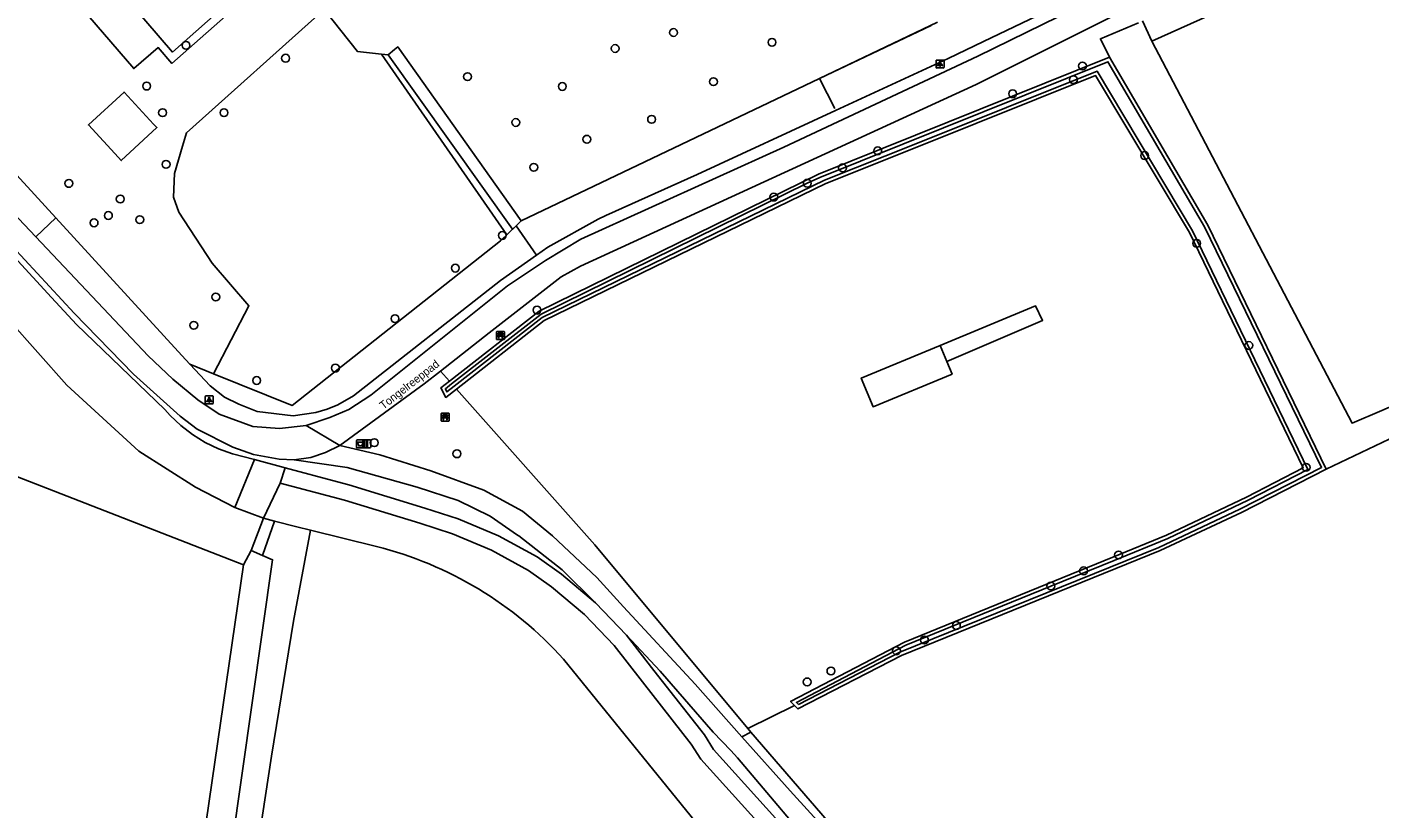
# Model space of a CAD drawing. Extents: x 160203 to 161526, y 379529 to 381797.
# Drawn here: x 161056.6 to 161225.7, y 381138.1 to 381235.8 of the extents above; entities that cross this region are included whole.
import ezdxf

# ---------------------------------------------------------------- set-up
doc = ezdxf.new("R2010")
doc.units = 0
for name, color, linetype in [('IMGEO_Afvalbak', 7, 'Continuous'), ('IMGEO_Bank', 7, 'Continuous'), ('IMGEO_Boom', 7, 'Continuous'), ('IMGEO_Bouwland', 7, 'Continuous'), ('IMGEO_Grasland_agrarisch', 7, 'Continuous'), ('IMGEO_Grasland_overig', 7, 'Continuous'), ('IMGEO_Groenvoorziening', 7, 'Continuous'), ('IMGEO_Haag', 7, 'Continuous'), ('IMGEO_Hek', 7, 'Continuous'), ('IMGEO_Lichtpunt', 7, 'Continuous'), ('IMGEO_Loofbos', 7, 'Continuous'), ('IMGEO_Openbare_ruimte_label', 7, 'Continuous'), ('IMGEO_Overkapping', 7, 'Continuous'), ('IMGEO_Pand', 7, 'Continuous'), ('IMGEO_Rijbaan_lokaal_gesloten', 7, 'Continuous'), ('IMGEO_Verkeersbordpaal', 7, 'Continuous'), ('IMGEO_Voetpad_halfverhard', 7, 'Continuous'), ('IMGEO_Waterloop', 7, 'Continuous')]:
    doc.layers.add(name, color=color, linetype=linetype)

msp = doc.modelspace()

# ---------------------------------------------------------------- linework, layer by layer
at = {"layer": 'IMGEO_Afvalbak'}
for p, q in [((161097.79, 381183.3), (161097.79, 381184.1)), ((161097.79, 381184.1), (161097.79, 381183.3)), ((161097.89, 381184.2), (161098.67, 381184.2)), ((161098.67, 381184.2), (161097.89, 381184.2)), ((161098.67, 381183.2), (161097.89, 381183.2)), ((161097.89, 381183.2), (161098.67, 381183.2)), ((161098.77, 381184.1), (161098.77, 381183.3)), ((161098.77, 381183.3), (161098.77, 381184.1))]:
    msp.add_line(p, q, dxfattribs=at)
msp.add_lwpolyline([(161097.93, 381183.91), (161098.63, 381183.91), (161098.48, 381183.44), (161098.08, 381183.44), (161097.93, 381183.91)], dxfattribs=at)
for centre, start, end in [((161097.89, 381184.1), 90, 180), ((161097.89, 381184.1), 90, 180), ((161097.89, 381183.3), 180, 270), ((161097.89, 381183.3), 180, 270), ((161098.67, 381184.1), 0, 90), ((161098.67, 381184.1), 360, 90), ((161098.67, 381183.3), 270, 0), ((161098.67, 381183.3), 270, 0)]:
    msp.add_arc(centre, 0.1, start, end, dxfattribs=at)
at = {"layer": 'IMGEO_Bank'}
for p, q in [((161115.28, 381196.83), (161115.28, 381197.67)), ((161115.28, 381197.67), (161115.28, 381196.83)), ((161115.36, 381197.75), (161116.2, 381197.75)), ((161116.2, 381197.75), (161115.36, 381197.75)), ((161116.21, 381196.76), (161115.37, 381196.76)), ((161115.37, 381196.76), (161116.21, 381196.76)), ((161115.59, 381197.26), (161115.59, 381197.37)), ((161115.98, 381197.15), (161115.59, 381197.15)), ((161115.92, 381197.37), (161115.64, 381197.37)), ((161115.64, 381197.37), (161115.64, 381197.26)), ((161115.64, 381197.26), (161115.92, 381197.26)), ((161115.93, 381197.26), (161115.93, 381197.37)), ((161115.97, 381197.37), (161115.97, 381197.26)), ((161116.28, 381197.68), (161116.28, 381196.84)), ((161116.28, 381196.84), (161116.28, 381197.68)), ((161108.37, 381186.62), (161108.37, 381187.46)), ((161108.37, 381187.46), (161108.37, 381186.62)), ((161108.44, 381187.55), (161109.29, 381187.55)), ((161109.29, 381187.55), (161108.44, 381187.55)), ((161109.3, 381186.55), (161108.45, 381186.55)), ((161108.45, 381186.55), (161109.3, 381186.55)), ((161109.07, 381186.94), (161108.67, 381186.94)), ((161108.68, 381187.05), (161108.68, 381187.16)), ((161108.72, 381187.16), (161108.72, 381187.05)), ((161109.01, 381187.16), (161108.73, 381187.16)), ((161108.73, 381187.05), (161109.01, 381187.05)), ((161109.02, 381187.05), (161109.02, 381187.16)), ((161109.06, 381187.16), (161109.06, 381187.05)), ((161109.37, 381187.47), (161109.37, 381186.63)), ((161109.37, 381186.63), (161109.37, 381187.47))]:
    msp.add_line(p, q, dxfattribs=at)
for points in [[(161115.53, 381197.15), (161115.39, 381197.15), (161115.5, 381197.26), (161115.59, 381197.26)], [(161115.59, 381197.37), (161115.5, 381197.37), (161115.5, 381197.53), (161116.06, 381197.53), (161116.06, 381197.37), (161115.98, 381197.37)], [(161115.58, 381197.15), (161115.58, 381196.94), (161115.54, 381196.94), (161115.54, 381197.15)], [(161115.98, 381197.26), (161116.06, 381197.26), (161116.18, 381197.15), (161116.04, 381197.15)], [(161116.03, 381197.15), (161116.03, 381196.94), (161115.99, 381196.94), (161115.99, 381197.15)], [(161108.62, 381186.94), (161108.47, 381186.94), (161108.59, 381187.05), (161108.67, 381187.05)], [(161108.67, 381187.16), (161108.59, 381187.16), (161108.59, 381187.33), (161109.15, 381187.33), (161109.15, 381187.16), (161109.07, 381187.16)], [(161108.67, 381186.94), (161108.67, 381186.73), (161108.62, 381186.73), (161108.62, 381186.94)], [(161109.07, 381187.05), (161109.15, 381187.05), (161109.26, 381186.94), (161109.12, 381186.94)], [(161109.12, 381186.94), (161109.12, 381186.73), (161109.07, 381186.73), (161109.07, 381186.94)]]:
    msp.add_lwpolyline(points, dxfattribs=at)
for centre, radius, start, end in [((161115.36, 381197.68), 0.0779, 92.4484, 184.2845), ((161115.36, 381197.68), 0.0779, 92.4484, 184.2845), ((161115.36, 381196.83), 0.0779, 182.4484, 274.2845), ((161115.36, 381196.83), 0.0779, 182.4484, 274.2845), ((161115.53, 381197.15), 0.00671, 2.8957, 87.1043), ((161115.59, 381197.15), 0.00671, 92.8957, 177.1043), ((161115.59, 381197.37), 0.00671, 2.8957, 87.1043), ((161115.59, 381197.26), 0.00671, 272.8957, 357.1043), ((161115.64, 381197.37), 0.00671, 92.8957, 177.1043), ((161115.64, 381197.26), 0.00671, 182.8957, 267.1043), ((161115.92, 381197.37), 0.00671, 2.8957, 87.1043), ((161115.92, 381197.26), 0.00671, 272.8957, 357.1043), ((161115.98, 381197.37), 0.00671, 92.8957, 177.1043), ((161115.98, 381197.26), 0.00671, 182.8957, 267.1043), ((161115.98, 381197.15), 0.00671, 2.8957, 87.1043), ((161116.04, 381197.15), 0.00671, 92.8957, 177.1043), ((161116.21, 381197.68), 0.0779, 2.4484, 94.2845), ((161116.21, 381197.68), 0.0779, 2.4484, 94.2845), ((161116.21, 381196.83), 0.0779, 272.4484, 4.2845), ((161116.21, 381196.83), 0.0779, 272.4484, 4.2845), ((161108.45, 381187.47), 0.0779, 92.4484, 184.2845), ((161108.45, 381187.47), 0.0779, 92.4484, 184.2845), ((161108.45, 381186.63), 0.0779, 182.4484, 274.2845), ((161108.45, 381186.63), 0.0779, 182.4484, 274.2845), ((161108.62, 381186.94), 0.00671, 2.8957, 87.1043), ((161108.67, 381187.16), 0.00671, 2.8957, 87.1043), ((161108.67, 381187.05), 0.00671, 272.8957, 357.1043), ((161108.67, 381186.94), 0.00671, 92.8957, 177.1043), ((161108.73, 381187.16), 0.00671, 92.8957, 177.1043), ((161108.73, 381187.05), 0.00671, 182.8957, 267.1043), ((161109.01, 381187.16), 0.00671, 2.8957, 87.1043), ((161109.01, 381187.05), 0.00671, 272.8957, 357.1043), ((161109.07, 381187.16), 0.00671, 92.8957, 177.1043), ((161109.07, 381187.05), 0.00671, 182.8957, 267.1043), ((161109.07, 381186.94), 0.00671, 2.8957, 87.1043), ((161109.12, 381186.94), 0.00671, 92.8957, 177.1043), ((161109.29, 381187.47), 0.0779, 2.4484, 94.2845), ((161109.29, 381187.47), 0.0779, 2.4484, 94.2845), ((161109.29, 381186.63), 0.0779, 272.4484, 4.2845), ((161109.29, 381186.63), 0.0779, 272.4484, 4.2845)]:
    msp.add_arc(centre, radius, start, end, dxfattribs=at)
at = {"layer": 'IMGEO_Boom'}
for centre in [(161137.41, 381235.13), (161076.48, 381233.53), (161149.72, 381233.91), (161088.93, 381231.92), (161130.11, 381233.14), (161188.51, 381230.95), (161071.57, 381228.44), (161111.67, 381229.62), (161123.52, 381228.39), (161142.4, 381228.99), (161187.38, 381229.24), (161179.79, 381227.48), (161073.56, 381225.11), (161081.23, 381225.11), (161117.7, 381223.89), (161134.67, 381224.28), (161126.58, 381221.79), (161162.93, 381220.34), (161196.28, 381219.75), (161074, 381218.65), (161119.95, 381218.28), (161158.53, 381218.21), (161154.12, 381216.29), (161061.85, 381216.27), (161068.27, 381214.32), (161149.94, 381214.56), (161065, 381211.34), (161066.79, 381212.25), (161070.71, 381211.74), (161116.02, 381209.76), (161202.78, 381208.77), (161110.15, 381205.68), (161080.21, 381202.07), (161120.35, 381200.43), (161077.46, 381198.53), (161102.61, 381199.36), (161209.31, 381196.01), (161095.16, 381193.18), (161085.32, 381191.63), (161100.01, 381183.85), (161110.34, 381182.47), (161216.46, 381180.77), (161193.02, 381169.81), (161188.65, 381167.83), (161184.56, 381165.93), (161172.76, 381160.99), (161168.76, 381159.18), (161165.27, 381157.83), (161154.11, 381153.94), (161157.08, 381155.31)]:
    msp.add_circle(centre, 0.489, dxfattribs=at)
at = {"layer": 'IMGEO_Bouwland'}
msp.add_lwpolyline([(161013.52, 381196.31), (161034.78, 381187.91), (161053.72, 381180.26), (161083.68, 381168.57)], dxfattribs=at)
at = {"layer": 'IMGEO_Grasland_agrarisch'}
for points in [[(161079.94, 381192.47), (161084.34, 381200.96), (161079.74, 381206.3), (161075.58, 381212.66), (161074.91, 381214.56), (161075.03, 381217.51), (161076.07, 381220.93), (161076.55, 381222.59), (161093.77, 381238.02)], [(161100.9, 381232.41), (161097.9, 381232.77), (161093.77, 381238.02)], [(161110.28, 381190.56), (161121.23, 381199.12), (161156.45, 381216.26), (161167.83, 381220.82), (161190.15, 381229.76), (161201.89, 381210.15), (161216.08, 381180.71), (161209.03, 381177.05), (161199.02, 381172.29), (161192.29, 381169.54), (161166.26, 381158.93), (161152.04, 381151.5), (161152.51, 381151.01)], [(161116.57, 381209.85), (161115.79, 381209.1), (161089.76, 381188.52), (161079.94, 381192.47)], [(161146.68, 381148.12), (161127.59, 381171.07), (161110.28, 381190.56)], [(161152.51, 381151.01), (161152.96, 381150.56), (161165.88, 381157.25), (161198.24, 381170.36), (161208.37, 381175.12), (161218.98, 381180.56)], [(161092.05, 381172.91), (161089.92, 381161.52), (161087.18, 381144.65), (161081.65, 381108.3), (161075.65, 381065.23), (161074.96, 381058.01)], [(161146.68, 381148.12), (161152.51, 381151.01)], [(161147.07, 381147.65), (161146.68, 381148.12)]]:
    msp.add_lwpolyline(points, dxfattribs=at)
at = {"layer": 'IMGEO_Grasland_overig'}
for points in [[(161367.83, 381310.71), (161294.02, 381278.51), (161294.05, 381277.58), (161293.85, 381277.49), (161232.69, 381250), (161197.17, 381234.04)], [(161120.28, 381207.29), (161121.7, 381208.28), (161128, 381211.79), (161128.95, 381212.25), (161140.38, 381217.39), (161157.67, 381225.4), (161171.71, 381231.9), (161176.13, 381234.01), (161209.5, 381250), (161221.3, 381255.61), (161240.99, 381264.56), (161246.29, 381266.89)], [(161036.74, 381238.05), (161041.49, 381232.45), (161060.22, 381211.97)], [(161118.36, 381211.58), (161155.67, 381229.38), (161169.59, 381236.02)], [(161195.51, 381236.36), (161190.76, 381234.35), (161191.89, 381232.05)], [(161197.17, 381234.04), (161196.03, 381236.58)], [(161263.14, 381204.2), (161225.91, 381187.89), (161222.21, 381186.3), (161197.17, 381234.04)], [(161101.77, 381232.33), (161100.9, 381232.41)], [(161100.9, 381232.41), (161116.57, 381209.85)], [(161191.89, 381232.05), (161155.51, 381217.41), (161120.61, 381200.3), (161109.4, 381191.55)], [(161191.89, 381232.05), (161204.16, 381211.06), (161218.98, 381180.56)], [(161060.22, 381211.97), (161057.71, 381209.57)], [(161060.22, 381211.97), (161075.97, 381194.74), (161076.98, 381193.66)], [(161116.57, 381209.85), (161117.29, 381210.54)], [(161120.28, 381207.29), (161117.74, 381210.98)], [(161076.98, 381193.66), (161079.5, 381190.95), (161081.3, 381189.56), (161083.08, 381188.65), (161085.4, 381187.75), (161089.86, 381187.22), (161092.71, 381187.64), (161094.12, 381188.05), (161095.48, 381188.6), (161097.43, 381189.73), (161115.8, 381204.13), (161120.28, 381207.29)], [(161170.74, 381195.99), (161182.64, 381200.98), (161183.52, 381199.13), (161171.56, 381194.01)], [(161109.4, 381191.55), (161108.29, 381192.8)], [(161218.98, 381180.56), (161227.72, 381184.71)], [(161085.05, 381181.74), (161088.87, 381180.71)], [(161086.17, 381174.41), (161082.58, 381175.75)], [(161145.96, 381147.09), (161147.07, 381147.65)], [(161175.22, 381116.21), (161164.8, 381127.1), (161147.07, 381147.65)]]:
    msp.add_lwpolyline(points, dxfattribs=at)
at = {"layer": 'IMGEO_Groenvoorziening'}
for points in [[(161081.37, 381241.6), (161083.54, 381239.04), (161074.73, 381231.27), (161073.02, 381233.25), (161069.95, 381230.62), (161054, 381249.19)], [(161076.98, 381193.66), (161079.94, 381192.47)], [(161109.4, 381191.55), (161108.33, 381190.71), (161108.95, 381189.52), (161110.28, 381190.56)], [(161086.05, 381169.75), (161087.55, 381174.03)]]:
    msp.add_lwpolyline(points, dxfattribs=at)
at = {"layer": 'IMGEO_Haag'}
for points in [[(161101.77, 381232.33), (161102.55, 381233), (161102.95, 381233.34), (161118.36, 381211.58)], [(161117.29, 381210.54), (161101.77, 381232.33)], [(161117.74, 381210.98), (161117.29, 381210.54)], [(161117.74, 381210.98), (161118.36, 381211.58)]]:
    msp.add_lwpolyline(points, dxfattribs=at)
at = {"layer": 'IMGEO_Hek'}
for points in [[(161170.4, 381236.41), (161155.67, 381229.38)], [(161155.67, 381229.38), (161118.36, 381211.58), (161117.74, 381210.98)], [(161155.67, 381229.38), (161157.55, 381225.64)], [(161036.27, 381227.49), (161059.7, 381201.99), (161062.8, 381198.62), (161073.83, 381188.01), (161074.49, 381187.27), (161075.83, 381185.99), (161077.3, 381184.86), (161078.89, 381183.89), (161080.56, 381183.09), (161082.31, 381182.47), (161085.05, 381181.74)], [(161117.74, 381210.98), (161115.79, 381209.1), (161089.76, 381188.52), (161079.94, 381192.47), (161076.98, 381193.66)], [(161227.72, 381184.71), (161218.98, 381180.56)], [(161141.26, 381147.32), (161134.95, 381155.38), (161131.53, 381159.79), (161127.66, 381163.81), (161123.39, 381167.41), (161120.35, 381169.56), (161115.55, 381172.21), (161110.5, 381174.35), (161106.32, 381175.67), (161096.85, 381178.57), (161095.42, 381178.96), (161088.87, 381180.71)], [(161088.27, 381178.8), (161086.17, 381174.41)], [(161086.17, 381174.41), (161084.61, 381170.36)], [(161142.41, 381145.5), (161155.58, 381130.91), (161167.52, 381117.41), (161170.51, 381113.56), (161172.88, 381109.71)]]:
    msp.add_lwpolyline(points, dxfattribs=at)
at = {"layer": 'IMGEO_Lichtpunt'}
for p, q in [((161170.21, 381231.6), (161170.21, 381230.79)), ((161170.21, 381231.6), (161170.21, 381230.79)), ((161171.11, 381231.69), (161170.31, 381231.69)), ((161171.11, 381231.69), (161170.31, 381231.69)), ((161170.31, 381230.7), (161171.11, 381230.7)), ((161170.31, 381230.7), (161171.11, 381230.7)), ((161171.21, 381230.79), (161171.21, 381231.6)), ((161171.21, 381230.79), (161171.21, 381231.6)), ((161078.89, 381189.6), (161078.89, 381188.8)), ((161078.89, 381189.6), (161078.89, 381188.8)), ((161079.8, 381189.7), (161078.99, 381189.7)), ((161079.8, 381189.7), (161078.99, 381189.7)), ((161078.99, 381188.7), (161079.8, 381188.7)), ((161078.99, 381188.7), (161079.8, 381188.7)), ((161079.89, 381188.8), (161079.89, 381189.6)), ((161079.89, 381188.8), (161079.89, 381189.6))]:
    msp.add_line(p, q, dxfattribs=at)
for points in [[(161170.59, 381231.26), (161170.62, 381231.24), (161170.44, 381230.97), (161170.4, 381231), (161170.59, 381231.26)], [(161170.69, 381231.22), (161170.73, 381231.22), (161170.73, 381230.89), (161170.69, 381230.89), (161170.69, 381231.22)], [(161170.8, 381231.24), (161170.84, 381231.26), (161171.02, 381231), (161170.98, 381230.97), (161170.8, 381231.24)], [(161079.27, 381189.27), (161079.31, 381189.24), (161079.12, 381188.98), (161079.08, 381189), (161079.27, 381189.27)], [(161079.37, 381189.22), (161079.42, 381189.22), (161079.42, 381188.9), (161079.37, 381188.9), (161079.37, 381189.22)], [(161079.48, 381189.24), (161079.52, 381189.27), (161079.71, 381189), (161079.67, 381188.98), (161079.48, 381189.24)]]:
    msp.add_lwpolyline(points, dxfattribs=at)
for centre in [(161170.71, 381231.4), (161079.39, 381189.4)]:
    msp.add_circle(centre, 0.0994, dxfattribs=at)
for centre, start, end in [((161170.31, 381231.6), 90, 180), ((161170.31, 381231.6), 90, 180), ((161170.31, 381230.79), 180, 270), ((161170.31, 381230.79), 180, 270), ((161171.11, 381231.6), 0, 90), ((161171.11, 381231.6), 0, 90), ((161171.11, 381230.79), 270, 0), ((161171.11, 381230.79), 270, 360), ((161078.99, 381189.6), 90, 180), ((161078.99, 381189.6), 90, 180), ((161078.99, 381188.8), 180, 270), ((161078.99, 381188.8), 180, 270), ((161079.8, 381189.6), 0, 90), ((161079.8, 381189.6), 0, 90), ((161079.8, 381188.8), 270, 0), ((161079.8, 381188.8), 270, 360)]:
    msp.add_arc(centre, 0.0946, start, end, dxfattribs=at)
at = {"layer": 'IMGEO_Loofbos'}
for points in [[(161036.27, 381227.49), (161059.7, 381201.99), (161062.8, 381198.62), (161073.83, 381188.01), (161074.49, 381187.27), (161075.83, 381185.99), (161077.3, 381184.86), (161078.89, 381183.89), (161080.56, 381183.09), (161082.31, 381182.47), (161085.05, 381181.74)], [(161082.58, 381175.75), (161077.67, 381178.3), (161070.58, 381182.79), (161061.58, 381191.03), (161050.68, 381203.28), (161037.87, 381219.57), (161034.13, 381223.39), (161013.62, 381201.68), (161010.51, 381202)], [(161085.05, 381181.74), (161082.58, 381175.75)], [(161088.27, 381178.8), (161088.87, 381180.71)], [(161088.87, 381180.71), (161095.42, 381178.96), (161096.85, 381178.57), (161106.32, 381175.67), (161110.5, 381174.35), (161115.55, 381172.21), (161120.35, 381169.56), (161123.39, 381167.41), (161127.66, 381163.81)], [(161088.27, 381178.8), (161086.17, 381174.41)], [(161170.65, 381109.5), (161168.86, 381112.42), (161165.98, 381116.13), (161154.09, 381129.57), (161140.81, 381144.29), (161139.62, 381146.16), (161133.53, 381153.96), (161130.01, 381158.48), (161126.29, 381162.35), (161122.17, 381165.83), (161119.29, 381167.86), (161114.68, 381170.41), (161109.81, 381172.47), (161105.7, 381173.77), (161096.3, 381176.65), (161088.27, 381178.8)], [(161087.55, 381174.03), (161086.17, 381174.41)], [(161087.55, 381174.03), (161090.35, 381173.33), (161092.05, 381172.91)], [(161092.05, 381172.91), (161100.28, 381170.88)], [(161071.99, 381061.64), (161087.31, 381169.21), (161086.05, 381169.75)], [(161083.68, 381168.57), (161084.61, 381170.36), (161086.05, 381169.75)], [(161083.68, 381168.57), (161078.99, 381136.45), (161073.21, 381098.18), (161068.35, 381062.52)], [(161131.53, 381159.79), (161134.95, 381155.38), (161141.26, 381147.32), (161142.41, 381145.5), (161155.58, 381130.91), (161167.52, 381117.41), (161170.51, 381113.56), (161172.88, 381109.71)], [(161123.68, 381156.77), (161140.71, 381135.77), (161151.89, 381124.85), (161169.34, 381106.63)]]:
    msp.add_lwpolyline(points, dxfattribs=at)
msp.add_arc((161088.86, 381125.48), 46.81, 41.9468, 75.8804, dxfattribs=at)
at = {"layer": 'IMGEO_Overkapping'}
for points in [[(161171.56, 381194.01), (161172.21, 381192.42), (161162.34, 381188.35), (161160.87, 381191.92), (161170.74, 381195.99)], [(161171.56, 381194.01), (161170.74, 381195.99)]]:
    msp.add_lwpolyline(points, dxfattribs=at)
at = {"layer": 'IMGEO_Pand'}
for points in [[(161081.37, 381241.6), (161080.58, 381240.92), (161082.11, 381239.13), (161074.81, 381232.68), (161059.95, 381250), (161051.4, 381259.95), (161051.8, 381260.26), (161048.63, 381263.95), (161054.29, 381268.75), (161057.43, 381265.04), (161058.22, 381265.7), (161071.8, 381250), (161074.81, 381246.52), (161075.34, 381247.05), (161077.32, 381244.78), (161078.04, 381245.4)], [(161072.44, 381223.68), (161072.85, 381223.24), (161068.4, 381219.13), (161068.07, 381219.49), (161064.29, 381223.59), (161068.74, 381227.69), (161072.44, 381223.68)]]:
    msp.add_lwpolyline(points, dxfattribs=at)
at = {"layer": 'IMGEO_Rijbaan_lokaal_gesloten'}
for points in [[(161108.29, 381192.8), (161114.38, 381197.57), (161123.38, 381204.59), (161125.79, 381205.94), (161175.21, 381228.65), (161209.02, 381245.57), (161218.78, 381250), (161257.16, 381267.43), (161261.42, 381269.36), (161301.19, 381286.35), (161354.19, 381309.33), (161381.5, 381321.67)], [(161255.77, 381270.11), (161236.8, 381261.86), (161224.01, 381256), (161211.76, 381250), (161175.45, 381232.2), (161151.18, 381220.82), (161125.81, 381209.31), (161121.42, 381206.63), (161116.65, 381203.45), (161099.6, 381189.8), (161096.83, 381188), (161094.45, 381187.01), (161091.51, 381186.01)], [(161057.71, 381209.57), (161047.7, 381220.16), (161037.65, 381231.68), (161035.45, 381234.1)], [(161040.9, 381223.4), (161062.52, 381200.04), (161069.91, 381192.43), (161075.74, 381187.18), (161077.9, 381185.55), (161082.33, 381183.3), (161084.93, 381182.39), (161088.15, 381181.8), (161089.99, 381181.7)], [(161091.51, 381186.01), (161088.19, 381185.61), (161084.83, 381185.87), (161080.63, 381187.42), (161077.97, 381189.22), (161074.83, 381191.81), (161071.75, 381194.73), (161057.71, 381209.57)], [(161095.7, 381183.5), (161106.27, 381191.23), (161108.29, 381192.8)], [(161095.7, 381183.5), (161091.51, 381186.01)], [(161089.99, 381181.7), (161092.07, 381182), (161093.94, 381182.61), (161095.7, 381183.5)]]:
    msp.add_lwpolyline(points, dxfattribs=at)
at = {"layer": 'IMGEO_Verkeersbordpaal'}
for p, q in [((161098.59, 381183.32), (161098.59, 381184.12)), ((161098.59, 381184.12), (161098.59, 381183.32)), ((161098.69, 381184.22), (161099.47, 381184.22)), ((161099.47, 381184.22), (161098.69, 381184.22)), ((161099.47, 381183.22), (161098.69, 381183.22)), ((161098.69, 381183.22), (161099.47, 381183.22)), ((161099.57, 381184.12), (161099.57, 381183.32)), ((161099.57, 381183.32), (161099.57, 381184.12))]:
    msp.add_line(p, q, dxfattribs=at)
msp.add_lwpolyline([(161099, 381184.09), (161099.15, 381184.09), (161099.15, 381183.34), (161099, 381183.34), (161099, 381184.09)], dxfattribs=at)
for centre, start, end in [((161098.69, 381184.12), 90, 180), ((161098.69, 381184.12), 90, 180), ((161098.69, 381183.32), 180, 270), ((161098.69, 381183.32), 180, 270), ((161099.47, 381184.12), 0, 90), ((161099.47, 381184.12), 360, 90), ((161099.47, 381183.32), 270, 0), ((161099.47, 381183.32), 270, 0)]:
    msp.add_arc(centre, 0.1, start, end, dxfattribs=at)
at = {"layer": 'IMGEO_Voetpad_halfverhard'}
for points in [[(161095.7, 381183.5), (161100.69, 381182.32), (161107.1, 381180.33), (161113.71, 381177.9), (161118.55, 381175.28), (161122.29, 381172.22), (161127.82, 381167), (161131.15, 381163.33), (161140.13, 381153.68), (161145.96, 381147.09)], [(161127.66, 381163.81), (161123.51, 381167.96), (161118.07, 381172.21), (161117.9, 381172.3), (161114.51, 381174.65), (161110.5, 381176.64), (161105.36, 381178.3), (161096.62, 381180.77), (161089.99, 381181.7)], [(161127.66, 381163.81), (161131.53, 381159.79)], [(161171.06, 381113.76), (161170.59, 381114.74), (161156.6, 381131.18), (161145.39, 381144.43), (161144.56, 381145.35), (161142.37, 381147.66), (161135.72, 381155.29), (161131.53, 381159.79)], [(161145.96, 381147.09), (161151.97, 381140.31), (161159.6, 381131.93), (161173.38, 381115.1)]]:
    msp.add_lwpolyline(points, dxfattribs=at)
at = {"layer": 'IMGEO_Waterloop'}
msp.add_lwpolyline([(161153.04, 381151.11), (161152.83, 381151.32), (161152.77, 381151.38), (161166.45, 381158.53), (161184.56, 381165.93), (161192.46, 381169.13), (161199.2, 381171.88), (161209.23, 381176.65), (161216.67, 381180.51), (161202.28, 381210.36), (161190.34, 381230.32), (161167.67, 381221.23), (161156.27, 381216.66), (161120.99, 381199.5), (161110, 381190.91), (161109.1, 381190.2), (161108.9, 381190.59), (161109.68, 381191.2), (161120.85, 381199.93), (161154.12, 381216.29), (161155.69, 381217), (161191.7, 381231.49), (161203.77, 381210.85), (161218.39, 381180.76), (161208.17, 381175.52), (161198.06, 381170.76), (161165.69, 381157.65), (161153.04, 381151.11)], dxfattribs=at)

# ---------------------------------------------------------------- texts
at = {"layer": 'IMGEO_Openbare_ruimte_label'}
msp.add_text('Tongelreeppad', height=1, rotation=38.0157, dxfattribs=at).set_placement((161101.16, 381187.96))

doc.saveas('drawing.dxf')
